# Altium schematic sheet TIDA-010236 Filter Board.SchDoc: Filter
size A4; ApprovedBy: Hely Zhang; CheckedBy: -; Author: Hely Zhang; CompanyName: Texas Instruments; DrawnBy: Hely Zhang; DocumentNumber: 1; SheetNumber: 1; SheetTotal: 1; PageSetup: Record=PageOptions¦CenterHorizontal=True¦CenterVertical=True¦PrintScale=0.93¦XCorrection=1.00¦YCorrection=1.00¦PrintKind=0¦BorderSize=5000000¦LeftOffset=0¦BottomOffset=0¦Orientation=2¦PaperLength=1000¦PaperWidth=1000¦Scale=100¦PaperSource=15¦PrintQuality=600¦MediaType=1¦DitherType=10¦PaperKind=Letter¦PrintScaleMode=1
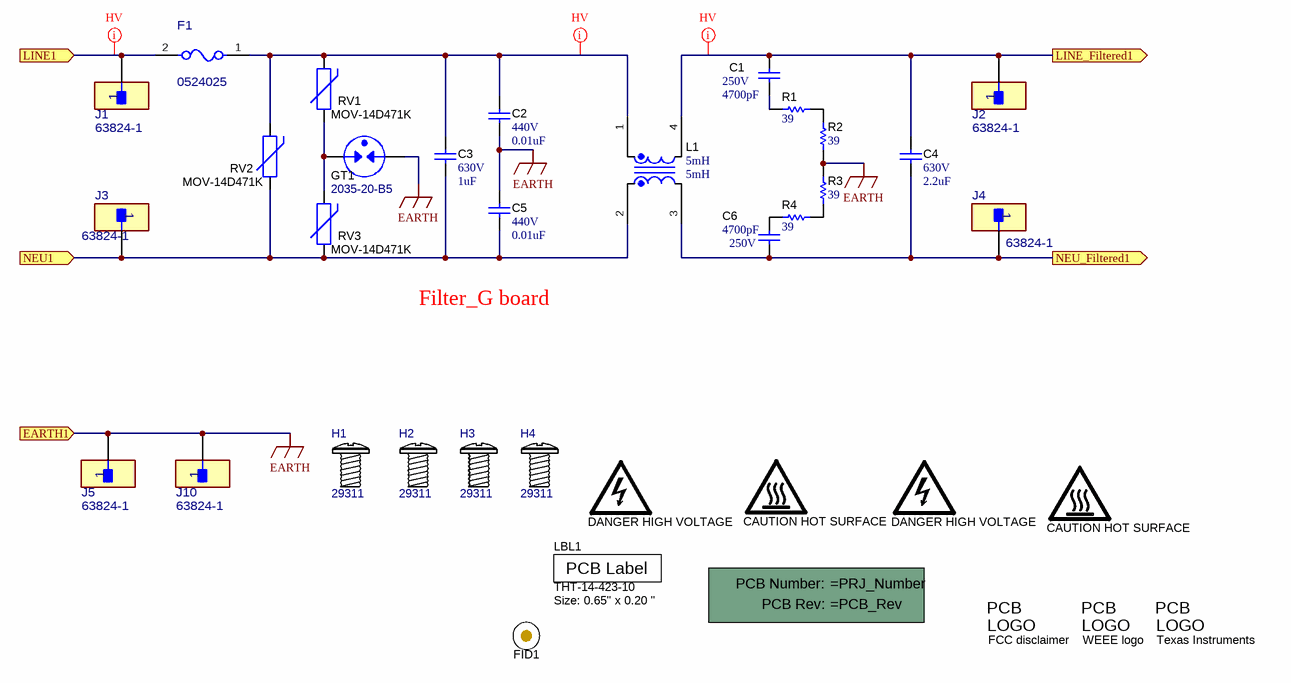
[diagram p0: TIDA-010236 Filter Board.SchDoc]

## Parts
!PCB1  Printed Circuit Board  (value not drawn)  (mechanical)
C1  VDC_V: 250V  ValueDisplayed: 4700pF  [KY_1000x500x1300]  (hidden comment: DE2E3KY472MB3BM02F)
C2  VDC_V: 440V  ValueDisplayed: 0.01uF  [VY2_1600x500]  (hidden comment: VY2103M63Y5US63V7)
C3  VDC_V: 630V  ValueDisplayed: 1uF  [B32924_19mm]  (hidden comment: B32924C3105M)
C4  VDC_V: 630V  ValueDisplayed: 2.2uF  [B32924_24.5mm]  (hidden comment: B32924C3225K)
C5  VDC_V: 440V  ValueDisplayed: 0.01uF  [VY2_1600x500]  (hidden comment: VY2103M63Y5US63V7)
C6  VDC_V: 250V  ValueDisplayed: 4700pF  [KY_1000x500x1300]  (hidden comment: DE2E3KY472MB3BM02F)
F1  0524025  [FP-0525025.MXEP_vm_AXIAL-MFG]
FID1  Fiducial  [Fiducial10-20]  (value not drawn)  (no BOM)
GT1  2035-20-B5  [GasTube_2035-20-B5]
H1  29311  [Keystone29311]
H2  29311  [Keystone29311]
H3  29311  [Keystone29311]
H4  29311  [Keystone29311]
J1  63824-1  [FP-63824-1_CONN_7MM92_3MM11-MFG]
J2  63824-1  [FP-63824-1_CONN_7MM92_3MM11-MFG]
J3  63824-1  [FP-63824-1_CONN_7MM92_3MM11-MFG]
J4  63824-1  [FP-63824-1_CONN_7MM92_3MM11-MFG]
J5  63824-1  [FP-63824-1_CONN_7MM92_3MM11-MFG]
J10  63824-1  [FP-63824-1_CONN_7MM92_3MM11-MFG]
L1  value 5mH  [WE-CMBNC_XXL]  (hidden comment: 7448062105)
LBL1  THT-14-423-10  Note: Size: 0.65" x 0.20 "  [Label_650x200]  (no BOM)
LOGO1  DANGER HIGH VOLTAGE  [IEC_HighVoltage_Small]  (no BOM)
LOGO2  CAUTION HOT SURFACE  [IEC_HotSurface_Small]  (no BOM)
LOGO3  DANGER HIGH VOLTAGE  [IEC_HighVoltage_Small]  (no BOM)
LOGO4  CAUTION HOT SURFACE  [IEC_HotSurface_Small]  (no BOM)
Logo5  FCC disclaimer  [FCC_disclaimer_stacked]  (no BOM)
Logo6  WEEE logo  [WEEE_Minimum]  (no BOM)
Logo7  Texas Instruments  [TI_Stacked_Overlay_Small]  (no BOM)
R1  ValueDisplayed: 39  [1210]  (hidden comment: RC1210JR-0739RL)
R2  ValueDisplayed: 39  [1210]  (hidden comment: RC1210JR-0739RL)
R3  ValueDisplayed: 39  [1210]  (hidden comment: RC1210JR-0739RL)
R4  ValueDisplayed: 39  [1210]  (hidden comment: RC1210JR-0739RL)
RV1  MOV-14D471K  [Bourns_MOV-14D621K]
RV2  MOV-14D471K  [Bourns_MOV-14D621K]
RV3  MOV-14D471K  [Bourns_MOV-14D621K]

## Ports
EARTH1 (in), LINE1 (in), LINE_Filtered1 (out), NEU1 (in), NEU_Filtered1 (out)

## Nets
EARTH: C2.2 C5.1 GT1.1 J5.1 J10.1 R2.2 R3.1 ; port EARTH1
LINE1: F1.2 J1.1 ; port LINE1
LINE_Filtered1: C1.1 C4.1 J2.1 L1.4 ; port LINE_Filtered1
NEU1: C3.2 C5.2 J3.1 L1.2 RV2.1 RV3.1 ; port NEU1
NEU_Filtered1: C4.2 C6.2 J4.1 L1.3 ; port NEU_Filtered1
NetC1_2: C1.2 R1.2
NetC2_1: C2.1 C3.1 F1.1 L1.1 RV1.2 RV2.2
NetC6_1: C6.1 R4.2
NetGT1_2: GT1.2 RV1.1 RV3.2
NetR1_1: R1.1 R2.1
NetR3_2: R3.2 R4.1

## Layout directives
net class HV: LINE1, LINE_Filtered1, NetC2_1

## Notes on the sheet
- Filter_G board

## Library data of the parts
!PCB1 = CMP-0003618-2: Manufacturer: Any
C1 C6 = CMP-0009611-1: CAP, CERM, 4700 pF, 250 V, +/- 20%, E, 10x5x13mm; Manufacturer: MuRata; TaMin_C: -40°C; Polarized: N; SizeAreaWB_mm2: 84; Value1: Unknown; U/M: EA; Value: 4700pF; TaMax_C: 125°C; SizeZ_mm: 13; SizeX_mm: 10; SizeY_mm: 5; SizeArea_mm2: 50; Cap_F: 4.7nF; AEC Category: Q200
C2 C5 = CMP-0009626-1: CAP, CERM, 0.01 uF, 440 V, +/- 20%, Y5U, D16xT5mm; Manufacturer: Vishay-Bccomponents; TaMin_C: -40°C; Polarized: N; SizeAreaWB_mm2: 126; Value1: Unknown; U/M: EA; Value: 0.01uF; TaMax_C: 125°C; SizeZ_mm: 20; SizeX_mm: 16; SizeY_mm: 5; Cap_Case: 16x5mm; SizeArea_mm2: 80; Cap_F: 10nF; AEC Category: Q200
C3 = CMP-0012432-3: CAP, Film, 1 uF, 630 V, +/- 20%, 0.018 ohm, TH; Manufacturer: Wurth; PartNumber: 890334027009; ESR_ohm: 0.018; Polarized: N; SizeAreaWB_mm2: 435.5; Value: 1uF; TaMax_C: 110°C; SizeZ_mm: 19; SizeX_mm: 11; SizeY_mm: 31.5; SizeArea_mm2: 346.5; Cap_F: 1µF; IRMS_A: 97mA; AEC Category: Q200
C4 = CMP-0012435-3: CAP, Film, 2.2 uF, 630 V, +/- 10%, TH; Manufacturer: WURTH; PartNumber: 890334027021CS; Polarized: N; SizeAreaWB_mm2: 536; Value1: Unknown; Value: 2.2uF; TaMax_C: 110°C; SizeZ_mm: 24.5; SizeX_mm: 14; SizeY_mm: 31.5; SizeArea_mm2: 441; Cap_F: 2.2µF; AEC Category: Q200
F1 = CMP-4956-0000-1: FUSE CERM 25A 250VAC 125VDC 3AB; Part Number: 0324025.MXP; Manufacturer: Littelfuse; AEC Grade: NA; Fuse Interrupt Dc Current: 10000A; AEC Qualified: No; VDC_V: 450V; Res_ohm: 3.8mΩ; MeltingTyp: 320A2Sec; Interrupt_DC: 10kA
FID1 = CMP-0077181-1: Fiducial mark.  There is nothing to buy or mount.
GT1 = CMP-0001871-2: Gas Discharge Tube, 2-Pole, TH; Manufacturer: Bourns; Value: 200V; CompType: Gas Tube
H1-H4 = CMP-0003639-1: Screw Pan Head M3; Manufacturer: Keystone; CompType: Hardware
J1-J5 J10 = CMP-0089624-1: Manufacturer: TE Connectivity; SizeZ_mm: 10.71mm; Conn Gender: Male; Conn Orientation: Straight; AEC Qualified: No; Import Ts: 1521847382; ContactFinish: Tin,Nickel; Current_A: 20A; Ciiva Ids: 766930
L1 = CMP-0013070-2: Coupled inductor, 5 mH,  A, 0.0065 ohm, TH; Manufacturer: Wurth Elektronik; DCR_ohm: 6.5m
LBL1 = CMP-0003625-1: Thermal Transfer Printable Labels, 0.650" W x 0.200" H - 10,000 per roll; Manufacturer: Brady; CompType: Label
LOGO1 LOGO3 = CMP-0074835-1: IEC 61010-1 High Voltage Warning; SymbolCreator: a0412235; Lib Reference: IEC_HighVoltage
LOGO2 LOGO4 = CMP-0074837-1: IEC 61010-1 Hot Surface Warning; SymbolCreator: a0412235; Lib Reference: IEC_HotSurface
Logo5 = CMP-0074847-1: FCC_disclaimer; Library Reference: Logo
Logo6 = CMP-0074769-1
Logo7 = CMP-0074838-1: Texas Instrument Corporate Signature; SymbolCreator: a0412235; Lib Reference: TI_Logo; Library Reference: Logo
R1-R4 = CMP-0083539-1: RES, 39, 5%, 0.5 W, 1210; Manufacturer: Yageo; Power_W: 500mW; TempCo: 100 ppm/C; SizeAreaWB_mm2: 14.7; Value_Code: 39R0; Value: 39; EIA_Code: E24; SizeX_mm: 3.2; SizeY_mm: 2.5; SizeZ_mm: 1.35; Value2: 0.5W; SizeArea_mm2: 8; AEC Qualified: N; VDC_V: 200V; AEC Category: Q200
RV1-RV3 = CMP-0001785-2: VARISTOR 558V 4.5KA, TH; PartNumber: 820543011; Manufacturer: WURTH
